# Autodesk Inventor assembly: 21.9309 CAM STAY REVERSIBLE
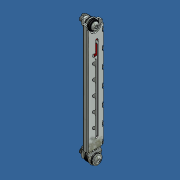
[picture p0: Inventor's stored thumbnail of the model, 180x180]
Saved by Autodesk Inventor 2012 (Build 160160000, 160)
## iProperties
Created: 2016-08
Part Number: 21.9309 CAM STAY REVERSIBLE
Document SubType Name: Assembly
Designer: Admin
Mass: 345.197 g
Surface Area: 482.087 cm^2
Volume: 47.6083 cm^3
Density: 7.25078 g/cm^3
Author: Admin
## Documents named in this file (6)
- C:\Andys Backup Data\ANDY'S INVENTOR\INVENTOR LIBRARIES\PARTS LIBRARY\HANDLES LOCKS STOPS\21.9309 CAM STAY REVERSIBLE.iam
- C:\Andys Backup Data\ANDY'S INVENTOR\INVENTOR LIBRARIES\PARTS LIBRARY\HANDLES LOCKS STOPS\SUBCOMPONENTS\21.9309_1 CAM STAY REVERSIBLE NO HARDWARE.iam
- C:\Andys Backup Data\ANDY'S INVENTOR\INVENTOR LIBRARIES\PARTS LIBRARY\FASTENING ELEMENTS\SCREWS OTHER\21.1189 POWER-LOCK SCREW.ipt
- C:\Andys Backup Data\ANDY'S INVENTOR\INVENTOR LIBRARIES\PARTS LIBRARY\FASTENING ELEMENTS\NUTS\21.1351_2 M8 SQUARE NUT POS FXG.ipt
- C:\Andys Backup Data\ANDY'S INVENTOR\INVENTOR LIBRARIES\PARTS LIBRARY\FASTENING ELEMENTS\WASHERS\21.9908_6 M8 Nylon Washer Black.ipt
- C:\Andys Backup Data\ANDY'S INVENTOR\INVENTOR LIBRARIES\PARTS LIBRARY\FASTENING ELEMENTS\BUTTON HEAD FLANGE SCREWS\21.9986 M8X30 BUTTON HEAD FLANGE.ipt
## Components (13 placed, 5 different names)
1. 21.9309_1 CAM STAY REVERSIBLE NO HARDWARE:1 [sub-assembly] — Mate:1, Angle:1, Angle:2, Insert:1, Insert:3, Insert:4, Angle:3, Mate:10, Angle:4
2. 21.1189 POWER-LOCK SCREW:1 — Mate:1, Angle:1, Mate:2, Mate:3, Insert:2
3. 21.1351_2 M8 SQUARE NUT POS FXG:1 — Mate:2, Mate:3, Angle:2, Mate:4, Flush:1
4. 21.9908_6 M8 Nylon Washer Black:1 — Insert:1
5. 21.9908_6 M8 Nylon Washer Black:2 — Insert:2
6. 21.9908_6 M8 Nylon Washer Black:3 — Insert:3, Mate:4
7. 21.9986 M8X30 BUTTON HEAD FLANGE:1 — Mate:5, Angle:3, Mate:6, Mate:7, Mate:8, Mate:9, Mate:11, Mate:12
8. 21.9908_6 M8 Nylon Washer Black:4 — Insert:4, Mate:5
9. 21.9908_6 M8 Nylon Washer Black:5 — Mate:7
10. 21.9908_6 M8 Nylon Washer Black:6 — Mate:8, Mate:13
11. 21.9908_6 M8 Nylon Washer Black:7 — Mate:9, Mate:10
12. 21.9908_6 M8 Nylon Washer Black:8 — Mate:6
13. 21.1351_2 M8 SQUARE NUT POS FXG:2 — Mate:11, Flush:1, Mate:12, Angle:4, Mate:13
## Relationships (22: Mate 13, Angle 4, Insert 4, Flush 1)
- Mate:1: 21.9309_1 CAM STAY REVERSIBLE NO HARDWARE:1 ↔ 21.1189 POWER-LOCK SCREW:1
- Angle:1: 21.9309_1 CAM STAY REVERSIBLE NO HARDWARE:1 ↔ 21.1189 POWER-LOCK SCREW:1
- Mate:2: 21.1189 POWER-LOCK SCREW:1 ↔ 21.1351_2 M8 SQUARE NUT POS FXG:1
- Mate:3: 21.1189 POWER-LOCK SCREW:1 ↔ 21.1351_2 M8 SQUARE NUT POS FXG:1
- Angle:2: 21.9309_1 CAM STAY REVERSIBLE NO HARDWARE:1 ↔ 21.1351_2 M8 SQUARE NUT POS FXG:1
- Insert:1: 21.9309_1 CAM STAY REVERSIBLE NO HARDWARE:1 ↔ 21.9908_6 M8 Nylon Washer Black:1
- Insert:2: 21.1189 POWER-LOCK SCREW:1 ↔ 21.9908_6 M8 Nylon Washer Black:2
- Insert:3: 21.9309_1 CAM STAY REVERSIBLE NO HARDWARE:1 ↔ 21.9908_6 M8 Nylon Washer Black:3
- Mate:4: 21.1351_2 M8 SQUARE NUT POS FXG:1 ↔ 21.9908_6 M8 Nylon Washer Black:3
- Insert:4: 21.9309_1 CAM STAY REVERSIBLE NO HARDWARE:1 ↔ 21.9908_6 M8 Nylon Washer Black:4
- Mate:5: 21.9986 M8X30 BUTTON HEAD FLANGE:1 ↔ 21.9908_6 M8 Nylon Washer Black:4
- Angle:3: 21.9309_1 CAM STAY REVERSIBLE NO HARDWARE:1 ↔ 21.9986 M8X30 BUTTON HEAD FLANGE:1
- Mate:6: 21.9986 M8X30 BUTTON HEAD FLANGE:1 ↔ 21.9908_6 M8 Nylon Washer Black:8
- Mate:7: 21.9986 M8X30 BUTTON HEAD FLANGE:1 ↔ 21.9908_6 M8 Nylon Washer Black:5
- Mate:8: 21.9986 M8X30 BUTTON HEAD FLANGE:1 ↔ 21.9908_6 M8 Nylon Washer Black:6
- Mate:9: 21.9986 M8X30 BUTTON HEAD FLANGE:1 ↔ 21.9908_6 M8 Nylon Washer Black:7
- Mate:10: 21.9309_1 CAM STAY REVERSIBLE NO HARDWARE:1 ↔ 21.9908_6 M8 Nylon Washer Black:7
- Mate:11: 21.9986 M8X30 BUTTON HEAD FLANGE:1 ↔ 21.1351_2 M8 SQUARE NUT POS FXG:2
- Flush:1: 21.1351_2 M8 SQUARE NUT POS FXG:1 ↔ 21.1351_2 M8 SQUARE NUT POS FXG:2
- Mate:12: 21.9986 M8X30 BUTTON HEAD FLANGE:1 ↔ 21.1351_2 M8 SQUARE NUT POS FXG:2
- Angle:4: 21.9309_1 CAM STAY REVERSIBLE NO HARDWARE:1 ↔ 21.1351_2 M8 SQUARE NUT POS FXG:2
- Mate:13: 21.9908_6 M8 Nylon Washer Black:6 ↔ 21.1351_2 M8 SQUARE NUT POS FXG:2
